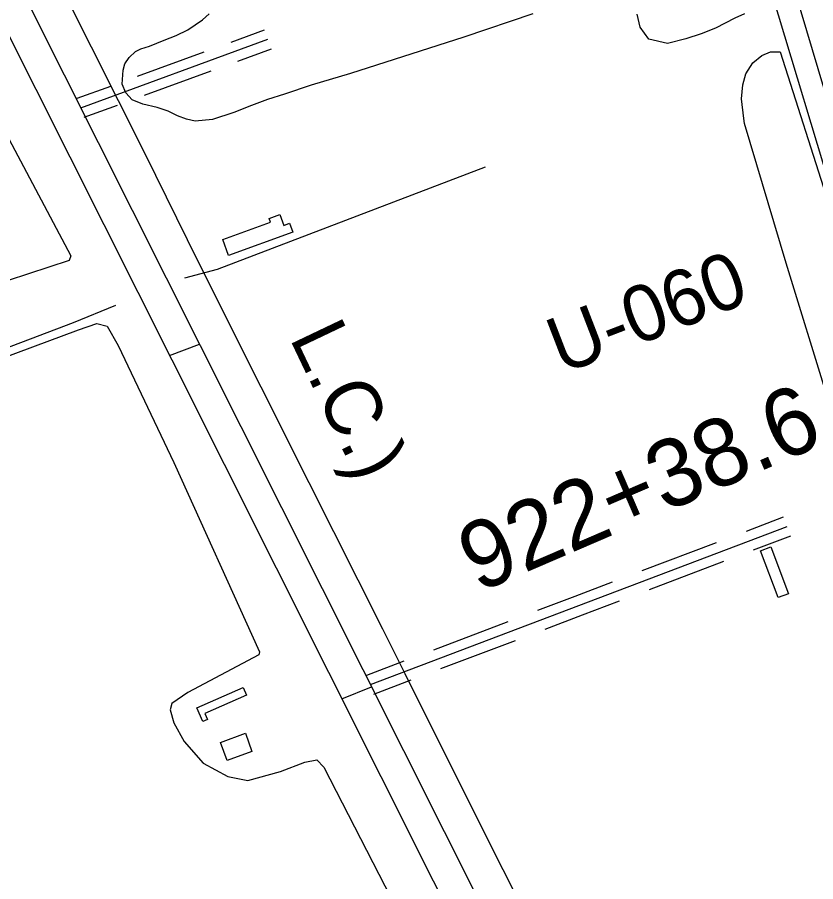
# Model space of a CAD drawing. Extents: x 3684037 to 3722149, y 433263 to 459021.
# Drawn here: x 3706676 to 3707859, y 440822 to 442103 of the extents above; entities that cross this region are included whole.
import ezdxf

# ---------------------------------------------------------------- set-up
doc = ezdxf.new("R2010")
doc.units = 0
for name, color, linetype in [('V-BLDG-OTLN', 7, 'Continuous'), ('V-LEVE-TOET', 7, 'Continuous'), ('V-RAIL-IDEN', 7, 'Continuous'), ('V-RAIL-TRAK', 7, 'Continuous'), ('V-RIVR-EDGE', 7, 'Continuous'), ('V-RIVR-RANG-IDEN', 7, 'Continuous'), ('V-ROAD-CNTR', 7, 'Continuous'), ('V-SITE-VEGE', 7, 'Continuous'), ('V-SURV-IDEN', 7, 'Continuous'), ('V-SURV-LINE', 7, 'Continuous'), ('V-TOPO-SHOR', 7, 'Continuous')]:
    doc.layers.add(name, color=color, linetype=linetype)

msp = doc.modelspace()

# ---------------------------------------------------------------- linework, layer by layer
at = {"layer": 'V-BLDG-OTLN'}
for points in [[(3706980.3, 441774.2), (3707050.8, 441799.7), (3707048.8, 441805.3), (3707064.7, 441811), (3707070.5, 441795.1), (3707079.3, 441798.3), (3707084.2, 441784.9), (3706988.9, 441750.4)], [(3707803.4, 441243.5), (3707777.4, 441312.8), (3707792.4, 441318.5), (3707818.5, 441249.2)], [(3706941.6, 441080), (3707010.4, 441110.1), (3707015.4, 441098.8), (3706953.6, 441071.7), (3706957.4, 441062.9), (3706950.5, 441059.8)], [(3706976.7, 441028.7), (3707013.7, 441042.3), (3707023.5, 441015.6), (3706986.5, 441002)]]:
    msp.add_lwpolyline(points, close=True, dxfattribs=at)
at = {"layer": 'V-LEVE-TOET'}
msp.add_lwpolyline([(3708256.8, 440826.4), (3708115.3, 441176.1), (3708024.4, 441423.1), (3707889.9, 441821.7), (3707794.6, 442138.2)], dxfattribs=at)
at = {"layer": 'V-RAIL-TRAK'}
msp.add_lwpolyline([(3706745.4, 442138.7), (3706864.5, 441901.8), (3706943.3, 441742.1), (3707036.6, 441555.8), (3707107.8, 441414.2), (3707216.7, 441197.4), (3707250, 441130.8), (3707344.6, 440941.6), (3707496.5, 440638.8), (3707529.5, 440573.1), (3707582.9, 440467), (3707626.4, 440388.6), (3707681.8, 440294.3), (3707685.6, 440288.5), (3707717.4, 440240.1), (3707784.4, 440141.8), (3707880, 440014), (3707886.8, 440006)], dxfattribs=at)
at = {"layer": 'V-RIVR-EDGE'}
msp.add_spline([(3705459.3, 448025.4), (3705478.2, 447991), (3705490.6, 447962.7), (3705497.9, 447946.9), (3705515.2, 447915.3), (3705550.2, 447853.8), (3705577.2, 447806.4), (3705592.1, 447777.2), (3705613, 447735.5), (3705627.1, 447702.7), (3705648.4, 447660.6), (3705670.9, 447613.3), (3705688.6, 447575.6), (3705703.1, 447542.8), (3705728.1, 447487.8), (3705750.2, 447433.1), (3705764.2, 447399.5), (3705787.6, 447350.5), (3705800.4, 447321.8), (3705823.8, 447277.7), (3705853.1, 447212.9), (3705867.2, 447179.7), (3705884.5, 447148.5), (3705906.2, 447095.5), (3705936, 447039.6), (3705952.5, 446996.3), (3705954.5, 446986.6), (3705964.5, 446959.1), (3705978.2, 446928.3), (3706001.9, 446883.8), (3706017.2, 446850.2), (3706031.3, 446824.3), (3706060.3, 446774.8), (3706084.9, 446736.8), (3706095.8, 446723.4), (3706096.2, 446720.2), (3706091.3, 446714.5), (3706089.7, 446713.3), (3706090.5, 446708.9), (3706096.1, 446705.6), (3706103, 446703.6), (3706108.6, 446696.7), (3706116.3, 446683.3), (3706130, 446657), (3706163.4, 446591.8), (3706169.4, 446575.6), (3706187.1, 446537.6), (3706212.8, 446473.6), (3706230.1, 446432.3), (3706247.4, 446398.3), (3706265.1, 446371.2), (3706278.8, 446345.3), (3706293.7, 446309.7), (3706314.6, 446262.3), (3706333.5, 446225.8), (3706356, 446180.1), (3706380.2, 446133.5), (3706396.3, 446102.4), (3706412.8, 446074.8), (3706429.7, 446038.8), (3706447, 445997.9), (3706455.4, 445962.3), (3706478.2, 445886.2), (3706492.7, 445852.2), (3706510.4, 445809.7), (3706528.1, 445771.7), (3706558.3, 445705.3), (3706582.8, 445657.1), (3706597.7, 445624.3), (3706628.3, 445558.3), (3706659.6, 445483), (3706677.7, 445432.8), (3706697, 445381), (3706750.1, 445262.4), (3706782.6, 445193.2), (3706806.8, 445141.8), (3706827.7, 445093.6), (3706851, 445029.3), (3706864.2, 444984.3), (3706871.8, 444949.5), (3706889.5, 444896.9), (3706899.9, 444865.8), (3706912.4, 444832.2), (3706928.8, 444798.2), (3706942.5, 444773.5), (3706966.3, 444725.3), (3706990.4, 444679.5), (3707017, 444624.5), (3707033.9, 444586), (3707080.5, 444482), (3707095.4, 444444.7), (3707112.3, 444405.1), (3707123.1, 444381.2), (3707171.4, 444273.5), (3707203.2, 444200.6), (3707218, 444163.8), (3707250.2, 444096.2), (3707257.4, 444074.3), (3707269.9, 444041.6), (3707288.4, 443990.6), (3707304, 443950.1), (3707343, 443838), (3707365.9, 443772), (3707378.7, 443728.7), (3707379.9, 443714.1), (3707381.1, 443702.8), (3707387.5, 443682.2), (3707398.3, 443657.1), (3707418.1, 443619), (3707439, 443578.5), (3707454.3, 443542.1), (3707473.1, 443492.7), (3707483.2, 443464.4), (3707531.1, 443368), (3707542.7, 443345), (3707550.8, 443323.9), (3707556.8, 443302.5), (3707556.8, 443297.6), (3707558.8, 443289.1), (3707568.4, 443273.3), (3707583.7, 443244.6), (3707593.8, 443221.9), (3707598.2, 443213.4), (3707609.5, 443204.9), (3707611.9, 443195.2), (3707611.9, 443180.6), (3707615.5, 443168.1), (3707621.9, 443150.3), (3707634.4, 443126.8), (3707648.1, 443102.1), (3707655.3, 443081.8), (3707660.5, 443073.3), (3707674.2, 443051.5), (3707678.6, 443034.1), (3707682.6, 443015.5), (3707689.5, 442998.5), (3707701.9, 442964.5), (3707714, 442928.4), (3707721.2, 442903.3), (3707726.4, 442888.8), (3707738.1, 442871.8), (3707743.7, 442857.2), (3707744.5, 442845.1), (3707747.3, 442826.1), (3707753.7, 442815.5), (3707763, 442801.3), (3707770.2, 442783.9), (3707772.6, 442762.1), (3707776.2, 442738.2), (3707779.8, 442720), (3707786.6, 442702.6), (3707805.5, 442663.3), (3707822.8, 442627.3), (3707832, 442599.4), (3707839.2, 442573.9), (3707845.7, 442561.3), (3707852.5, 442552.4), (3707860.2, 442541.9), (3707869.5, 442530.6), (3707886.4, 442507.9), (3707898.9, 442479.9), (3707916.1, 442434.6), (3707928.6, 442395.8), (3707943.4, 442356.5), (3707965.6, 442316.4), (3707989.7, 442269), (3708009.8, 442227.7), (3708024.7, 442192.5), (3708061.3, 442114.4), (3708074.2, 442088.5), (3708094.3, 442045.6), (3708116, 441996.6), (3708126.1, 441968.3), (3708137.7, 441927.8), (3708147.3, 441899.5), (3708157.8, 441868.3), (3708179.1, 441812.4), (3708204, 441746.9), (3708227.7, 441693.8), (3708249.8, 441646.1), (3708265.1, 441615.3), (3708271.5, 441595.9), (3708278.4, 441582.1), (3708308.1, 441508.4), (3708330.6, 441457.8), (3708349.9, 441405.2), (3708369.6, 441340.1), (3708384, 441295.6), (3708395.3, 441268.4), (3708411.8, 441234.8), (3708423.4, 441209.3), (3708441.1, 441169.7), (3708458.4, 441135.2), (3708469.3, 441110.5), (3708475.3, 441089.1), (3708486.9, 441061.6), (3708507.1, 441017.4), (3708523.5, 440978.6), (3708539.2, 440935.7), (3708564.1, 440883.1), (3708587.1, 440841.3), (3708595.1, 440826.8), (3708600.4, 440809.4), (3708606.7, 440778.2), (3708615.6, 440755.1), (3708636.9, 440692), (3708652.9, 440644.3), (3708673.4, 440592), (3708688.7, 440554.4), (3708706, 440506.6), (3708725.7, 440462.9), (3708743.4, 440422.4), (3708759.4, 440387.6), (3708800.1, 440293.3), (3708821, 440246.3), (3708835, 440211.5), (3708849.1, 440180.4), (3708876.1, 440124.9), (3708892.2, 440093.7), (3708912.3, 440054.9), (3708922.3, 440031), (3708932, 439999.8), (3708939.2, 439978.8), (3708948, 439954.1), (3708952.4, 439931.8), (3708956, 439911.6), (3708960, 439899.5), (3708969.6, 439870.3), (3708986.9, 439829.8), (3708999.4, 439794.2), (3709014.7, 439755.4), (3709034.7, 439705.2), (3709046.8, 439671.6), (3709063.3, 439633.1), (3709075.8, 439614.5), (3709093.1, 439592.6), (3709106, 439574.4), (3709121.7, 439548.9), (3709151.5, 439484.1), (3709171.6, 439447.3), (3709197.4, 439407.6), (3709211.1, 439376.8), (3709222.3, 439350.1), (3709240.4, 439308.8), (3709252.9, 439281.7), (3709266.1, 439254.9), (3709271, 439245.6), (3709296.3, 439199.9), (3709313.2, 439159), (3709331.3, 439114.9), (3709341.3, 439082.5), (3709360.3, 439046.5), (3709378.8, 439008.8), (3709407.7, 438944.4), (3709416.4, 438923.6)], degree=3, dxfattribs=at)
at = {"layer": 'V-ROAD-CNTR'}
for points in [[(3706492.4, 442521.2), (3706946.8, 441617.1), (3707489, 440536.5), (3707877, 439759.9), (3708257.7, 438990.5)], [(3706450.1, 442499.9), (3706904.6, 441595.9), (3707446.7, 440515.3), (3707834.7, 439738.8), (3708246.6, 438913.6)], [(3706992.4, 442066.7), (3707041.9, 442084.8)], [(3706769.8, 441969.4), (3707047, 442070.8)], [(3707002.7, 442038.6), (3707052.2, 442056.7)], [(3706853.7, 442016.1), (3706952.8, 442052.3)], [(3706864, 441987.9), (3706963.1, 442024.1)], [(3706764.6, 441983.5), (3706814.1, 442001.6)], [(3706774.9, 441955.3), (3706824.4, 441973.4)], [(3706901.4, 441602.2), (3706945.8, 441619.2)], [(3707756.3, 441342.1), (3707811.5, 441363)], [(3707199, 441114.5), (3707816.8, 441349)], [(3707601.9, 441283.4), (3707712.2, 441325.3)], [(3707767, 441314), (3707822.1, 441334.9)], [(3707612.5, 441255.4), (3707722.8, 441297.3)], [(3707502.6, 441245.8), (3707557.7, 441266.7)], [(3707447.4, 441224.8), (3707502.6, 441245.8)], [(3707513.2, 441217.7), (3707568.4, 441238.7)], [(3707293, 441166.2), (3707403.3, 441208.1)], [(3707458.1, 441196.8), (3707513.2, 441217.7)], [(3707303.6, 441138.2), (3707413.9, 441180.1)], [(3707193.7, 441128.6), (3707248.8, 441149.5)], [(3707204.3, 441100.5), (3707259.5, 441121.4)], [(3707156.8, 441093.2), (3707200.6, 441111.3)]]:
    msp.add_lwpolyline(points, dxfattribs=at)
at = {"layer": 'V-SITE-VEGE'}
for points in [[(3707439.5, 442108.6), (3707337.5, 442074.2), (3707169.4, 442020.4), (3707111, 442002.7), (3707071.6, 441989.5), (3707046.6, 441981.5), (3707022.7, 441972.9), (3706996.5, 441962.5), (3706964.9, 441952.2), (3706939.3, 441949.5), (3706926.3, 441952.7), (3706913.3, 441957.6), (3706899.1, 441964.3), (3706883.1, 441969.8), (3706861.8, 441974.8), (3706845.9, 441980.9), (3706836.5, 441991.7), (3706831.3, 442004.3), (3706832.7, 442025), (3706835.2, 442034.5), (3706841.3, 442043.9), (3706850.9, 442052.7), (3706858.7, 442056.8), (3706871.8, 442060.8), (3706893.3, 442069.4), (3706911.2, 442076.4), (3706928.5, 442085.1), (3706950, 442099.6), (3706960.2, 442108.4)], [(3707753.6, 442108.4), (3707739.3, 442102), (3707710.6, 442087.5), (3707689.1, 442078.9), (3707666.5, 442071.4), (3707639.1, 442064.6), (3707611.8, 442070.9), (3707599, 442088.9), (3707594.4, 442107.9)], [(3706203.1, 441431), (3706766.2, 441640.3), (3706793.7, 441649.5), (3706809.1, 441645.8), (3706825.3, 441617.1), (3706907.6, 441443.9), (3707034.8, 441163.2), (3707033.6, 441158.5), (3706928.4, 441102.7), (3706904.5, 441086.4), (3706902, 441076.9), (3706907.7, 441057.9), (3706922.8, 441030.4), (3706950.9, 440998), (3706987.5, 440978.5), (3707017.1, 440972.2), (3707066, 440985.9), (3707101.8, 440999.7), (3707119.6, 441003.1), (3707130.2, 440992.2), (3707301.9, 440657.6)]]:
    msp.add_lwpolyline(points, dxfattribs=at)
for points in [[(3705817.9, 441374.7), (3705641.5, 441704.4), (3705641.7, 441713.2), (3705645.8, 441719.5), (3705658.2, 441725.8), (3706079.7, 441881.7), (3706591.3, 442075.2), (3706663.1, 441923.5), (3706754.8, 441750.1), (3706752.4, 441743), (3706571.1, 441683.5), (3706192.8, 441527.7), (3705834.7, 441382.3)], [(3707753.4, 441946.3), (3707752.3, 441953.4), (3707749.1, 441982.5), (3707751.2, 442003.3), (3707755.5, 442019.9), (3707765.8, 442035.8), (3707779, 442046.9), (3707792.1, 442052.1), (3707804, 442052.5), (3707806.4, 442052.5), (3707877.9, 441827.8), (3707939.5, 441615.6), (3707951.3, 441565), (3707952.8, 441535.9), (3707944.8, 441518.8), (3707931.7, 441511.8), (3707916.8, 441507.2), (3707903.1, 441505.6), (3707894.2, 441508.7), (3707886.6, 441517.7), (3707876.8, 441538.6), (3707815.1, 441738.9)]]:
    msp.add_lwpolyline(points, close=True, dxfattribs=at)
at = {"layer": 'V-SURV-LINE'}
msp.add_lwpolyline([(3707997.2, 441576.4), (3707592.3, 442933.3)], dxfattribs=at)
at = {"layer": 'V-TOPO-SHOR'}
msp.add_line((3706821.1, 441676.3), (3706758.5, 441650.6), dxfattribs=at)
for points in [[(3707369.2, 441881.3), (3706972.1, 441729.7), (3706923.6, 441716.9)], [(3706758.5, 441650.6), (3706449.6, 441533.6), (3706090.5, 441406.4), (3705863.4, 441314.6), (3705847.1, 441306), (3705841.5, 441301.9)]]:
    msp.add_lwpolyline(points, dxfattribs=at)

# ---------------------------------------------------------------- texts
at = {"layer": 'V-RAIL-IDEN'}
msp.add_text('L.C.)', height=83, rotation=295.4633, dxfattribs=at).set_placement((3707078.5, 441628.5))
at = {"layer": 'V-RIVR-RANG-IDEN'}
msp.add_text('U-060', height=83, rotation=21.1143, dxfattribs=at).set_placement((3707482.1, 441573.8))
at = {"layer": 'V-SURV-IDEN'}
msp.add_text('922+38.6', height=100, rotation=23.3103, dxfattribs=at).set_placement((3707358.4, 441250))

doc.saveas('drawing.dxf')
